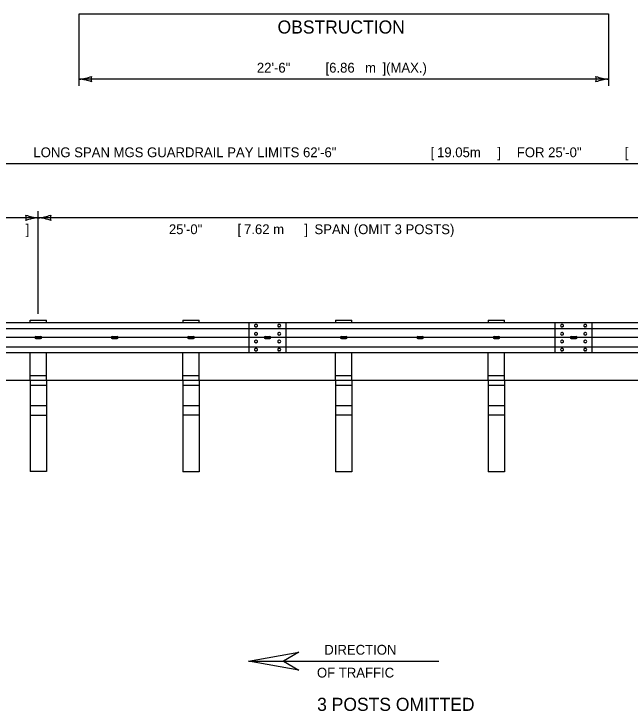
# Model space of a CAD drawing. Extents: x 49991.4 to 50044.5, y 49987.6 to 50011.4.
# Drawn here: x 50026.981 to 50030.751, y 50004.142 to 50008.408 of the extents above; entities that cross this region are included whole.
import ezdxf

# ---------------------------------------------------------------- set-up
doc = ezdxf.new("R2010")
doc.units = 0
for name, color, linetype in [('Level 1', 7, 'Continuous'), ('Level 2', 7, 'Continuous'), ('Level 3', 7, 'Continuous'), ('Level 4', 7, 'Continuous'), ('Level 5', 7, 'Continuous')]:
    doc.layers.add(name, color=color, linetype=linetype)

msp = doc.modelspace()

# ---------------------------------------------------------------- linework, layer by layer
at = {"layer": 'Level 1'}
for p, q in [((50027.3802, 50007.9692), (50027.3802, 50008.4083)), ((50027.3802, 50008.4083), (50030.618, 50008.4083)), ((50030.618, 50008.4083), (50030.618, 50007.9692)), ((50027.0802, 50006.5203), (50027.0802, 50006.5336)), ((50027.0802, 50006.5336), (50027.1802, 50006.5336)), ((50027.1802, 50006.5203), (50027.1802, 50006.5336)), ((50028.0147, 50006.5336), (50028.0147, 50006.5203)), ((50028.0147, 50006.5336), (50028.1146, 50006.5336)), ((50028.1146, 50006.5203), (50028.1146, 50006.5336)), ((50028.9491, 50006.5336), (50028.9491, 50006.5203)), ((50028.9491, 50006.5336), (50029.0491, 50006.5336)), ((50029.0491, 50006.5203), (50029.0491, 50006.5336)), ((50029.8836, 50006.5336), (50029.8836, 50006.5203)), ((50029.8836, 50006.5336), (50029.9835, 50006.5336)), ((50029.9835, 50006.5203), (50029.9835, 50006.5336)), ((50023.8525, 50006.5203), (50035.1185, 50006.5203)), ((50023.8525, 50006.4843), (50035.1185, 50006.4843)), ((50028.4197, 50006.335), (50028.4197, 50006.5196)), ((50028.4639, 50006.508), (50028.4603, 50006.508)), ((50028.4639, 50006.4929), (50028.4603, 50006.4929)), ((50028.6061, 50006.508), (50028.6025, 50006.508)), ((50028.6061, 50006.4929), (50028.6025, 50006.4929)), ((50030.2922, 50006.335), (50030.2922, 50006.5196)), ((50030.3364, 50006.508), (50030.3328, 50006.508)), ((50030.3364, 50006.4929), (50030.3328, 50006.4929)), ((50030.4786, 50006.508), (50030.475, 50006.508)), ((50030.4786, 50006.4929), (50030.475, 50006.4929)), ((50028.4639, 50006.4581), (50028.4603, 50006.4581)), ((50028.4639, 50006.443), (50028.4603, 50006.443)), ((50028.6061, 50006.4581), (50028.6025, 50006.4581)), ((50028.6061, 50006.443), (50028.6025, 50006.443)), ((50030.3364, 50006.4581), (50030.3328, 50006.4581)), ((50030.3364, 50006.443), (50030.3328, 50006.443)), ((50030.4786, 50006.4581), (50030.475, 50006.4581)), ((50030.4786, 50006.443), (50030.475, 50006.443)), ((50027.1156, 50006.4342), (50027.1448, 50006.4342)), ((50027.1156, 50006.4217), (50027.1448, 50006.4217)), ((50027.5829, 50006.4342), (50027.612, 50006.4342)), ((50027.5829, 50006.4217), (50027.612, 50006.4217)), ((50028.0501, 50006.4342), (50028.0792, 50006.4342)), ((50028.0501, 50006.4217), (50028.0792, 50006.4217)), ((50028.4639, 50006.4116), (50028.4603, 50006.4116)), ((50028.4639, 50006.3965), (50028.4603, 50006.3965)), ((50028.5183, 50006.4342), (50028.5475, 50006.4342)), ((50028.5183, 50006.4217), (50028.5475, 50006.4217)), ((50028.6061, 50006.4116), (50028.6025, 50006.4116)), ((50028.6061, 50006.3965), (50028.6025, 50006.3965)), ((50028.9845, 50006.4342), (50029.0137, 50006.4342)), ((50028.9845, 50006.4217), (50029.0137, 50006.4217)), ((50029.4517, 50006.4342), (50029.4809, 50006.4342)), ((50029.4517, 50006.4217), (50029.4809, 50006.4217)), ((50029.919, 50006.4342), (50029.9481, 50006.4342)), ((50029.919, 50006.4217), (50029.9481, 50006.4217)), ((50030.3364, 50006.4116), (50030.3328, 50006.4116)), ((50030.3364, 50006.3965), (50030.3328, 50006.3965)), ((50030.3908, 50006.4342), (50030.42, 50006.4342)), ((50030.3908, 50006.4217), (50030.42, 50006.4217)), ((50030.4786, 50006.4116), (50030.475, 50006.4116)), ((50030.4786, 50006.3965), (50030.475, 50006.3965)), ((50023.8525, 50006.3717), (50035.1185, 50006.3717)), ((50028.4639, 50006.3617), (50028.4603, 50006.3617)), ((50028.6061, 50006.3617), (50028.6025, 50006.3617)), ((50030.3364, 50006.3617), (50030.3328, 50006.3617)), ((50030.4786, 50006.3617), (50030.475, 50006.3617)), ((50023.8525, 50006.3357), (50035.1185, 50006.3357)), ((50027.0802, 50006.1659), (50027.0802, 50006.3357)), ((50027.1802, 50006.1659), (50027.1802, 50006.3357)), ((50028.0147, 50006.1659), (50028.0147, 50006.3357)), ((50028.1146, 50006.1659), (50028.1146, 50006.3357)), ((50028.4639, 50006.3466), (50028.4603, 50006.3466)), ((50028.6061, 50006.3466), (50028.6025, 50006.3466)), ((50028.9491, 50006.1659), (50028.9491, 50006.3357)), ((50029.049, 50006.1659), (50029.049, 50006.3357)), ((50029.8836, 50006.1659), (50029.8836, 50006.3357)), ((50029.9835, 50006.1659), (50029.9835, 50006.3357)), ((50030.3364, 50006.3466), (50030.3328, 50006.3466)), ((50030.4786, 50006.3466), (50030.475, 50006.3466)), ((50035.1185, 50006.1659), (50023.8525, 50006.1659)), ((50028.4164, 50004.4474), (50029.5818, 50004.4474))]:
    msp.add_line(p, q, dxfattribs=at)
msp.add_lwpolyline([(50028.7238, 50004.3932), (50028.4164, 50004.4474), (50028.7238, 50004.502), (50028.6301, 50004.4474)], close=True, dxfattribs=at)
for centre, start, end in [((50027.1156, 50006.428), 90, 180), ((50027.1156, 50006.428), 180, 270), ((50027.1448, 50006.428), 360, 90), ((50027.1448, 50006.428), 270, 0), ((50027.5829, 50006.428), 90, 180), ((50027.5829, 50006.428), 180, 270), ((50027.612, 50006.428), 360, 90), ((50027.612, 50006.428), 270, 0), ((50028.0501, 50006.428), 90, 180), ((50028.0501, 50006.428), 180, 270), ((50028.0792, 50006.428), 360, 90), ((50028.0792, 50006.428), 270, 0), ((50028.5183, 50006.428), 90, 180), ((50028.5183, 50006.428), 180, 270), ((50028.5475, 50006.428), 360, 90), ((50028.5475, 50006.428), 270, 0), ((50028.9845, 50006.428), 90, 180), ((50028.9845, 50006.428), 180, 270), ((50029.0137, 50006.428), 360, 90), ((50029.0137, 50006.428), 270, 0), ((50029.4517, 50006.428), 90, 180), ((50029.4517, 50006.428), 180, 270), ((50029.4809, 50006.428), 360, 90), ((50029.4809, 50006.428), 270, 0), ((50029.919, 50006.428), 90, 180), ((50029.919, 50006.428), 180, 270), ((50029.9481, 50006.428), 360, 90), ((50029.9481, 50006.428), 270, 0), ((50030.3908, 50006.428), 90, 180), ((50030.3908, 50006.428), 180, 270), ((50030.42, 50006.428), 360, 90), ((50030.42, 50006.428), 270, 0)]:
    msp.add_arc(centre, 0.00625, start, end, dxfattribs=at)
for centre, start_param, end_param in [((50028.4603, 50006.5004), 1.570796, 4.712389), ((50028.4639, 50006.5004), 4.712389, 7.853982), ((50028.6025, 50006.5004), 1.570796, 4.712389), ((50028.6061, 50006.5004), 4.712389, 7.853982), ((50030.3328, 50006.5004), 1.570796, 4.712389), ((50030.3364, 50006.5004), 4.712389, 7.853982), ((50030.475, 50006.5004), 1.570796, 4.712389), ((50030.4786, 50006.5004), 4.712389, 7.853982), ((50028.4603, 50006.4505), 1.570796, 4.712389), ((50028.4639, 50006.4505), 4.712389, 7.853982), ((50028.6025, 50006.4505), 1.570796, 4.712389), ((50028.6061, 50006.4505), 4.712389, 7.853982), ((50030.3328, 50006.4505), 1.570796, 4.712389), ((50030.3364, 50006.4505), 4.712389, 7.853982), ((50030.475, 50006.4505), 1.570796, 4.712389), ((50030.4786, 50006.4505), 4.712389, 7.853982), ((50028.4603, 50006.404), 1.570796, 4.712389), ((50028.4639, 50006.404), 4.712389, 7.853982), ((50028.6025, 50006.404), 1.570796, 4.712389), ((50028.6061, 50006.404), 4.712389, 7.853982), ((50030.3328, 50006.404), 1.570796, 4.712389), ((50030.3364, 50006.404), 4.712389, 7.853982), ((50030.475, 50006.404), 1.570796, 4.712389), ((50030.4786, 50006.404), 4.712389, 7.853982), ((50028.4603, 50006.3541), 1.570796, 4.712389), ((50028.4639, 50006.3541), 4.712389, 7.853982), ((50028.6025, 50006.3541), 1.570796, 4.712389), ((50028.6061, 50006.3541), 4.712389, 7.853982), ((50030.3328, 50006.3541), 1.570796, 4.712389), ((50030.3364, 50006.3541), 4.712389, 7.853982), ((50030.475, 50006.3541), 1.570796, 4.712389), ((50030.4786, 50006.3541), 4.712389, 7.853982)]:
    msp.add_ellipse(centre, major_axis=(0.00756, 0), ratio=0.998676, start_param=start_param, end_param=end_param, dxfattribs=at)
at = {"layer": 'Level 3'}
for p, q in [((50030.618, 50008.0092), (50027.3802, 50008.0092)), ((50035.1185, 50007.4915), (50023.8525, 50007.4915)), ((50027.1302, 50006.5736), (50027.1302, 50007.2007)), ((50027.1302, 50007.1607), (50025.2577, 50007.1607)), ((50030.868, 50007.1607), (50027.1302, 50007.1607))]:
    msp.add_line(p, q, dxfattribs=at)
for centre, radius, start, end in [((50027.3687, 50008.2419), 0.233, 272.8273, 292.0772), ((50027.5084, 50008.0092), 0.0548, 162.1388, 197.8612), ((50030.6272, 50008.2313), 0.2223, 247.456, 267.6395), ((50030.4898, 50008.0092), 0.0548, 342.1388, 17.8612), ((50027.371, 50007.787), 0.2223, 67.456, 87.6395), ((50030.6295, 50007.7764), 0.233, 92.8273, 112.0772), ((50027.1394, 50007.3829), 0.2223, 247.456, 267.6395), ((50027.002, 50007.1607), 0.0548, 342.1388, 17.8612), ((50027.1187, 50007.3934), 0.233, 272.8273, 292.0772), ((50027.2584, 50007.1607), 0.0548, 162.1388, 197.8612), ((50027.1417, 50006.928), 0.233, 92.8273, 112.0772), ((50027.1211, 50006.9386), 0.2223, 67.456, 87.6395)]:
    msp.add_arc(centre, radius, start, end, dxfattribs=at)
at = {"layer": 'Level 4'}
for p, q in [((50028.6461, 50006.335), (50028.6461, 50006.5196)), ((50030.5186, 50006.335), (50030.5186, 50006.5196)), ((50027.0802, 50006.195), (50027.1802, 50006.195)), ((50028.0147, 50006.1957), (50028.1146, 50006.1957)), ((50028.9491, 50006.1957), (50029.049, 50006.1957)), ((50029.8836, 50006.1957), (50029.9835, 50006.1957)), ((50027.0802, 50006.1659), (50027.0802, 50005.6078)), ((50027.1802, 50006.1659), (50027.1802, 50005.6078)), ((50028.0147, 50006.1659), (50028.0147, 50005.6067)), ((50028.1146, 50006.1659), (50028.1146, 50005.6067)), ((50028.9491, 50006.1659), (50028.9491, 50005.6067)), ((50029.049, 50006.1659), (50029.049, 50005.6067)), ((50029.8836, 50006.1659), (50029.8836, 50005.6067)), ((50029.9835, 50006.1659), (50029.9835, 50005.6067)), ((50027.0802, 50006.1367), (50027.1802, 50006.1367)), ((50028.0147, 50006.1374), (50028.1146, 50006.1374)), ((50028.9491, 50006.1374), (50029.049, 50006.1374)), ((50029.8836, 50006.1374), (50029.9835, 50006.1374)), ((50028.0147, 50006.0127), (50028.1146, 50006.0127)), ((50028.9491, 50006.0127), (50029.049, 50006.0127)), ((50029.8836, 50006.0127), (50029.9835, 50006.0127)), ((50027.0802, 50006.0121), (50027.1802, 50006.0121)), ((50027.0802, 50005.9538), (50027.1802, 50005.9538)), ((50028.0147, 50005.9544), (50028.1146, 50005.9544)), ((50028.9491, 50005.9544), (50029.049, 50005.9544)), ((50029.8836, 50005.9544), (50029.9835, 50005.9544)), ((50027.1802, 50005.6078), (50027.0802, 50005.6078)), ((50028.1146, 50005.6067), (50028.0147, 50005.6067)), ((50029.049, 50005.6067), (50028.9491, 50005.6067)), ((50029.9835, 50005.6067), (50029.8836, 50005.6067))]:
    msp.add_line(p, q, dxfattribs=at)
at = {"layer": 'Level 5'}
msp.add_line((50035.1185, 50006.428), (50023.8525, 50006.428), dxfattribs=at)

# ---------------------------------------------------------------- texts
at = {"layer": 'Level 2'}
for s, height, p in [('OBSTRUCTION', 0.08, (50028.5942, 50008.2883)), ('22\'-6" ', 0.06, (50028.4676, 50008.0492)), ('[6.86', 0.06, (50028.8876, 50008.0492)), (']', 0.06, (50029.2362, 50008.0492)), (' (MAX.)', 0.06, (50029.2358, 50008.0492)), (' m', 0.06, (50029.1073, 50008.0492)), ('LONG SPAN MGS GUARDRAIL PAY LIMITS 62\'-6" ', 0.06, (50027.1003, 50007.5315)), ('[', 0.06, (50029.5303, 50007.5315)), ('19.05m', 0.06, (50029.5699, 50007.5315)), (']  ', 0.06, (50029.9389, 50007.5315)), ('FOR 25\'-0" ', 0.06, (50030.058, 50007.5315)), ('[', 0.06, (50030.718, 50007.5315)), (']', 0.06, (50027.0532, 50007.0607)), ('25\'-0" ', 0.06, (50027.9292, 50007.0607)), ('[', 0.06, (50028.3492, 50007.0607)), ('7.62 m', 0.06, (50028.3889, 50007.0607)), (']', 0.06, (50028.7579, 50007.0607)), (' SPAN (OMIT 3 POSTS)', 0.06, (50028.7976, 50007.0607)), ('DIRECTION', 0.06, (50028.8802, 50004.4874)), ('OF TRAFFIC', 0.06, (50028.8351, 50004.3474)), ('3 POSTS OMITTED', 0.08, (50028.8363, 50004.1435))]:
    msp.add_text(s, height=height, dxfattribs=at).set_placement(p)

doc.saveas('drawing.dxf')
